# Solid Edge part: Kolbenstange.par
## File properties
Username: psaghy
Dokumentum tartalom típus: 0
Author: psaghy
Last saved by: psaghy
Revision: 83
Sűrűség: 0,000 kg/m^3
Pontosság: 0,990
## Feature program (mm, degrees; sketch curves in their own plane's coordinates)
base feature "unnamed BaseFeature 1"
thread "unnamed Thread 1"
chamfer "Letörés_1" setback 0.4
sketch for "Kihúzás_1" plane through (46.75, 0, 0) normal (1, 0, 0) x-axis (0, 1, 0)
  circle centre (0, 0) radius 4
extrude "Kihúzás_1" add finite 25.5 along -normal
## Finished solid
Body 1: solid body, 7 faces, 6 edges, 0 vertices.
  Faces by surface: cylinder 3, plane 3, cone 1
  Edges by curve: circle 6
Bounding box of the edges (mm): 263.750 x 8.000 x 8.000, from (-217, -4, -4) to (46.75, 4, 4).
Cylindrical faces by radius (mm): R2 x2, R4 x1
Conical faces (half-angle, radius in mm at the cone's reference point): 45 deg R1.6 x1
Planar faces by outward normal: +x 1, -x 2
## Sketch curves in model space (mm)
circle centre (46.75, 0, 0) radius 4
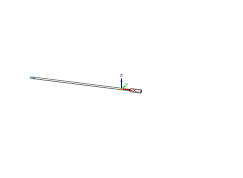
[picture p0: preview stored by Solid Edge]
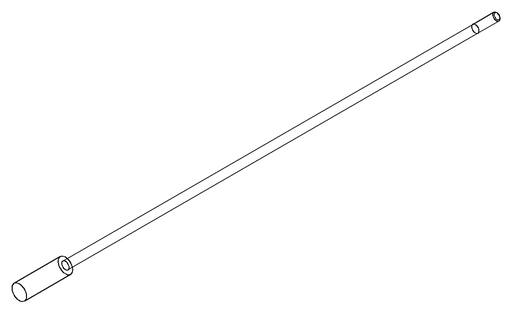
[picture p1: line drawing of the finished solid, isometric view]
